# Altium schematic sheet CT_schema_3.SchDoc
size 313 x 185 mm
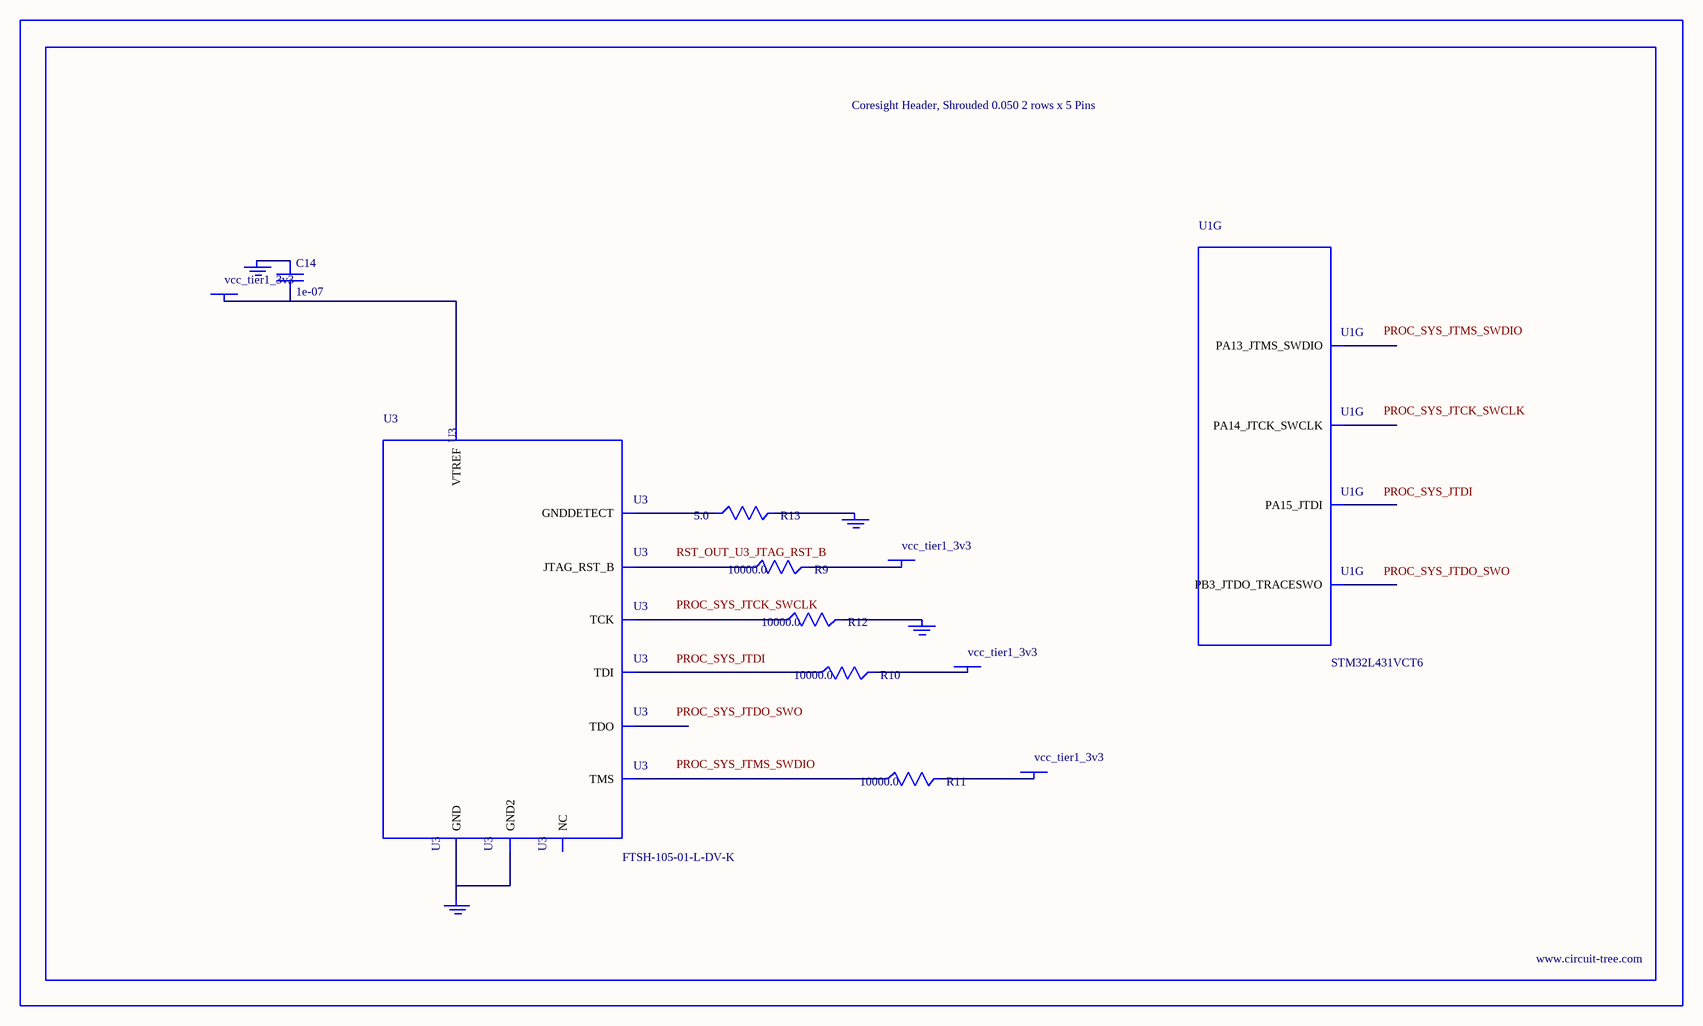
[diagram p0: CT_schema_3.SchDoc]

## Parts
BORDER2  (no value)
C14  1e-07  [C0402]
GND_INSTANCE_2_0  (no value)
GND_INSTANCE_2_1  (no value)
GND_INSTANCE_2_2  (no value)
GND_INSTANCE_2_3  (no value)
POWER_INSTANCE_2_0  vcc_tier1_3v3
POWER_INSTANCE_2_1  vcc_tier1_3v3
POWER_INSTANCE_2_2  vcc_tier1_3v3
POWER_INSTANCE_2_3  vcc_tier1_3v3
R9  10000.0  [R0603]
R10  10000.0  [R0603]
R11  10000.0  [R0603]
R12  10000.0  [R0603]
R13  5.0  [R0603]
U1  STM32L431VCT6  [LQFP100]  (part G of 8)
U3  FTSH-105-01-L-DV-K  [SAMTEC_FTSH-105-01-L-DV-K]

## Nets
NetC14_1: C14.1 GND_INSTANCE_2_0.0(GND)
NetC14_2: C14.2 POWER_INSTANCE_2_0.0(PWR) U3.1(VTREF)
NetGND_INSTANCE_2_1_0: GND_INSTANCE_2_1.0(GND) R12.2
NetGND_INSTANCE_2_2_0: GND_INSTANCE_2_2.0(GND) R13.2
NetGND_INSTANCE_2_3_0: GND_INSTANCE_2_3.0(GND) U3.3(GND) U3.5(GND2)
NetPOWER_INSTANCE_2_1_0: POWER_INSTANCE_2_1.0(PWR) R11.2
NetPOWER_INSTANCE_2_2_0: POWER_INSTANCE_2_2.0(PWR) R10.2
NetPOWER_INSTANCE_2_3_0: POWER_INSTANCE_2_3.0(PWR) R9.2
NetR9_1: R9.1 U3.10(JTAG_RST_B)
NetR10_1: R10.1 U3.8(TDI)
NetR11_1: R11.1 U3.2(TMS)
NetR12_1: R12.1 U3.4(TCK)
NetR13_1: R13.1 U3.9(GNDDETECT)

Not connected (* = marked no-connect by the designer): U1 72(PA13_JTMS_SWDIO) 76(PA14_JTCK_SWCLK) 77(PA15_JTDI) 89(PB3_JTDO_TRACESWO); U3 6(TDO) 7(NC)

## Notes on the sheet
- Labels drawn without touching a wire or pin: PROC_SYS_JTCK_SWCLK, PROC_SYS_JTDI, PROC_SYS_JTDO_SWO, PROC_SYS_JTMS_SWDIO, RST_OUT_U3_JTAG_RST_B

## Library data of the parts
BORDER2 = BORDER_PAGE2
C14 = C0402C104K3RACTU
GND_INSTANCE_2_0-GND_INSTANCE_2_3 = GND
POWER_INSTANCE_2_0-POWER_INSTANCE_2_3 = PWR
R9-R12 = RC0603JR-0710KL
R13 = ERJ-3GEYJ5R1V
